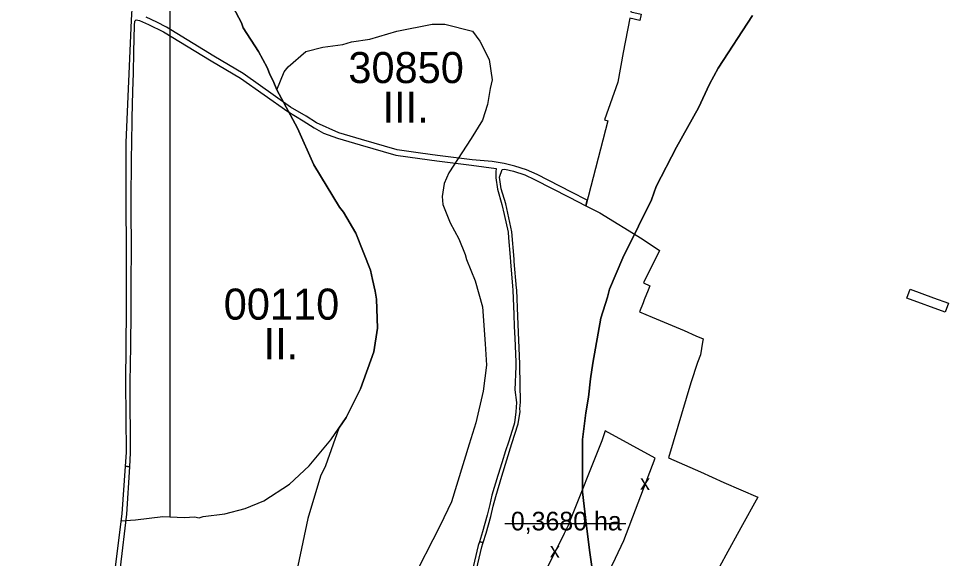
# Model space of a CAD drawing. Extents: x -555509 to -553014, y -1186753 to -1182560.
# Drawn here: x -555107 to -554508, y -1185200 to -1184853 of the extents above; entities that cross this region are included whole.
import ezdxf

# ---------------------------------------------------------------- set-up
doc = ezdxf.new("R2010")
doc.units = 0
for name, color, linetype in [('LEG_6_ZPF', 7, 'Continuous'), ('Level 29', 7, 'Continuous'), ('Level 52', 7, 'Continuous'), ('pěší_tr', 7, 'Continuous'), ('ZABOR_ke_zruseni', 7, 'Continuous')]:
    doc.layers.add(name, color=color, linetype=linetype)

msp = doc.modelspace()

# ---------------------------------------------------------------- linework, layer by layer
at = {"layer": 'LEG_6_ZPF'}
for p, q in [((-555009.53, -1184791.53), (-555009.53, -1185173.66)), ((-554656.56, -1184884.62), (-554634.5, -1184850.75)), ((-554952.5, -1184874), (-554962.25, -1184858.75)), ((-554662.06, -1184894.88), (-554656.56, -1184884.62)), ((-554669.25, -1184910.12), (-554662.06, -1184894.88)), ((-554732, -1185045.75), (-554727.75, -1185032.13)), ((-554737.12, -1185074.62), (-554732, -1185045.75))]:
    msp.add_line(p, q, dxfattribs=at)
for points in [[(-555009.53, -1184791.53), (-555000, -1184799.13), (-554997, -1184800.62), (-554988.06, -1184811.25), (-554972.38, -1184838.38), (-554963.5, -1184855.38), (-554962.25, -1184858.75), (-554952.5, -1184874), (-554946.94, -1184884.25), (-554944.88, -1184889.25), (-554943.12, -1184892.75), (-554940.62, -1184898.63)], [(-554962.25, -1184858.75), (-554963.5, -1184855.38), (-554972.38, -1184838.38), (-554988.06, -1184811.25)], [(-554634.5, -1184850.75), (-554656.56, -1184884.62), (-554662.06, -1184894.88), (-554669.25, -1184910.12), (-554683.25, -1184935.5), (-554696.38, -1184961), (-554699.38, -1184969.38), (-554707.81, -1184986.38), (-554718, -1185006.75), (-554726.5, -1185027.12), (-554727.75, -1185032.13), (-554732, -1185045.75), (-554737.12, -1185074.62), (-554738.81, -1185084.75), (-554740.06, -1185096.62), (-554741.75, -1185106.75), (-554743.88, -1185123.75), (-554743.88, -1185157.63), (-554741.31, -1185179.75), (-554739.19, -1185196.62), (-554737.12, -1185210.25)], [(-554940.62, -1184898.63), (-554935.94, -1184887.13), (-554933.38, -1184883.75), (-554921.94, -1184874), (-554910.94, -1184871.13), (-554898.19, -1184869.38), (-554892.69, -1184867.63), (-554880.81, -1184866), (-554863.44, -1184860.88), (-554840.56, -1184856.25), (-554832.5, -1184856.25), (-554814.69, -1184860.88), (-554810, -1184867.25), (-554804.06, -1184879.13), (-554801.94, -1184892.25), (-554803.25, -1184897.75), (-554804.94, -1184908), (-554808.31, -1184918.12), (-554815.5, -1184930), (-554829.94, -1184952), (-554832.94, -1184958.88), (-554834.19, -1184967.38), (-554833.75, -1184972.38), (-554829.12, -1184984.25), (-554823.56, -1184994.5), (-554819.38, -1185004.63), (-554818.5, -1185008), (-554813, -1185021.63), (-554808.31, -1185038.5), (-554806.62, -1185062.25), (-554805.75, -1185075.88), (-554807.88, -1185092.75), (-554812.56, -1185113.13), (-554816.81, -1185126.75), (-554828.25, -1185164), (-554835.44, -1185179.25), (-554854.56, -1185216.62)], [(-554940.62, -1184898.63), (-554943.12, -1184892.75), (-554944.88, -1184889.25), (-554946.94, -1184884.25), (-554952.5, -1184874)], [(-554900.75, -1185116.5), (-554896.06, -1185109.75), (-554886.75, -1185091.12), (-554878.25, -1185067.38), (-554875.75, -1185052.12), (-554876.56, -1185033.5), (-554877.44, -1185028.38), (-554879.12, -1185020.75), (-554880.38, -1185014.75), (-554889.75, -1184991), (-554897.75, -1184977.5), (-554900.31, -1184974.12), (-554916.88, -1184947), (-554927.44, -1184923.25), (-554940.62, -1184898.63)], [(-554696.38, -1184961), (-554683.25, -1184935.5), (-554669.25, -1184910.12)], [(-554707.81, -1184986.38), (-554699.38, -1184969.38), (-554696.38, -1184961)], [(-554727.75, -1185032.13), (-554726.5, -1185027.12), (-554718, -1185006.75), (-554707.81, -1184986.38)], [(-554740.06, -1185096.62), (-554738.81, -1185084.75), (-554737.12, -1185074.62)], [(-554732.88, -1185223.88), (-554737.12, -1185210.25), (-554739.19, -1185196.62), (-554741.31, -1185179.75), (-554743.88, -1185157.63), (-554743.88, -1185123.75), (-554741.75, -1185106.75), (-554740.06, -1185096.62)], [(-555009.53, -1185173.66), (-555000, -1185174), (-554993.62, -1185173.75), (-554990.62, -1185174.25), (-554988.06, -1185173.38), (-554974.12, -1185171.63), (-554960.94, -1185168.25), (-554949.06, -1185163.25), (-554932.56, -1185152.62), (-554919.81, -1185140.75), (-554905.81, -1185124.12), (-554900.75, -1185116.5)]]:
    msp.add_lwpolyline(points, dxfattribs=at)
at = {"layer": 'Level 29'}
for points in [[(-555038.12, -1184688.4), (-555038.12, -1184695.12), (-555038.56, -1184698.5), (-555036, -1184723.88), (-555031.75, -1184742.5), (-555030.06, -1184749.25), (-555026.69, -1184766.25), (-555024.12, -1184774.75), (-555015.69, -1184786.63), (-555000, -1184799.13), (-554997, -1184800.62), (-554988.06, -1184811.25), (-554972.38, -1184838.38), (-554963.5, -1184855.38), (-554962.25, -1184858.75), (-554952.5, -1184874), (-554946.94, -1184884.25), (-554944.88, -1184889.25), (-554943.12, -1184892.75), (-554940.62, -1184898.63)], [(-554634.5, -1184850.75), (-554656.56, -1184884.62), (-554662.06, -1184894.88), (-554669.25, -1184910.12), (-554683.25, -1184935.5), (-554696.38, -1184961), (-554699.38, -1184969.38), (-554707.81, -1184986.38), (-554718, -1185006.75), (-554726.5, -1185027.12), (-554727.75, -1185032.13), (-554732, -1185045.75), (-554737.12, -1185074.62), (-554738.81, -1185084.75), (-554740.06, -1185096.62), (-554741.75, -1185106.75), (-554743.88, -1185123.75), (-554743.88, -1185157.63), (-554741.31, -1185179.75), (-554739.19, -1185196.62), (-554737.12, -1185210.25)], [(-554940.62, -1184898.63), (-554935.94, -1184887.13), (-554933.38, -1184883.75), (-554921.94, -1184874), (-554910.94, -1184871.13), (-554898.19, -1184869.38), (-554892.69, -1184867.63), (-554880.81, -1184866), (-554863.44, -1184860.88), (-554840.56, -1184856.25), (-554832.5, -1184856.25), (-554814.69, -1184860.88), (-554810, -1184867.25), (-554804.06, -1184879.13), (-554801.94, -1184892.25), (-554803.25, -1184897.75), (-554804.94, -1184908), (-554808.31, -1184918.12), (-554815.5, -1184930), (-554829.94, -1184952), (-554832.94, -1184958.88), (-554834.19, -1184967.38), (-554833.75, -1184972.38), (-554829.12, -1184984.25), (-554823.56, -1184994.5), (-554819.38, -1185004.63), (-554818.5, -1185008), (-554813, -1185021.63), (-554808.31, -1185038.5), (-554806.62, -1185062.25), (-554805.75, -1185075.88), (-554807.88, -1185092.75), (-554812.56, -1185113.13), (-554816.81, -1185126.75), (-554828.25, -1185164), (-554835.44, -1185179.25), (-554854.56, -1185216.62)], [(-554940.62, -1184898.63), (-554927.44, -1184923.25), (-554916.88, -1184947), (-554900.31, -1184974.12), (-554897.75, -1184977.5), (-554889.75, -1184991), (-554880.38, -1185014.75), (-554879.12, -1185020.75), (-554877.44, -1185028.38), (-554876.56, -1185033.5), (-554875.75, -1185052.12), (-554878.25, -1185067.38), (-554886.75, -1185091.12), (-554896.06, -1185109.75), (-554900.75, -1185116.5)], [(-555040.99, -1185176.15), (-555031.75, -1185175.63), (-555014, -1185173.5), (-555000, -1185174), (-554993.62, -1185173.75), (-554990.62, -1185174.25), (-554988.06, -1185173.38), (-554974.12, -1185171.63), (-554960.94, -1185168.25), (-554949.06, -1185163.25), (-554932.56, -1185152.62), (-554919.81, -1185140.75), (-554905.81, -1185124.12), (-554900.75, -1185116.5)], [(-554900.75, -1185116.5), (-554909.25, -1185140.75), (-554912.62, -1185147.5), (-554920.69, -1185174.63), (-554930.44, -1185220.38), (-554938.06, -1185273), (-554940.62, -1185285.25)]]:
    msp.add_lwpolyline(points, dxfattribs=at)
at = {"layer": 'Level 52'}
for points in [[(-554690.37, -1184660.23), (-554694.47, -1184658.87), (-554696.6, -1184667.81), (-554697.96, -1184701.13), (-554700.16, -1184781.85), (-554712.7, -1184848.47), (-554706.04, -1184849.97), (-554706.92, -1184853.88), (-554713.44, -1184852.4), (-554717.6, -1184874.5)], [(-554717.6, -1184874.5), (-554721.19, -1184893.59), (-554729.6, -1184917.85), (-554727.63, -1184918.52), (-554741.83, -1184973.43), (-554732.66, -1184977.91)], [(-554732.66, -1184977.91), (-554705.36, -1184994.55), (-554694.27, -1185002.2), (-554704.58, -1185023.01), (-554700.42, -1185024.78), (-554701.54, -1185027.57), (-554704.08, -1185033.86), (-554704.89, -1185035.88), (-554707.18, -1185041.55), (-554699.04, -1185044.99), (-554678.5, -1185053.7), (-554670.81, -1185057.05), (-554666.18, -1185059.07), (-554666.61, -1185061.26), (-554667.89, -1185069.33), (-554669.8, -1185074.16), (-554674.12, -1185087.36), (-554688.49, -1185135.67), (-554667.86, -1185144.71), (-554652.87, -1185151.49), (-554630.97, -1185160.97)], [(-554517.89, -1185032.52), (-554508.3, -1185036.11), (-554510.48, -1185041.91), (-554535.01, -1185032.73), (-554532.83, -1185026.92), (-554517.89, -1185032.52)], [(-554630.97, -1185160.97), (-554641.88, -1185180.77), (-554651.54, -1185198.32)], [(-554651.54, -1185198.32), (-554660.04, -1185213.75), (-554661.31, -1185215.81), (-554671.87, -1185232.89), (-554682.43, -1185249.97), (-554688.42, -1185259.67), (-554691.95, -1185267.5), (-554694.99, -1185274.23)]]:
    msp.add_lwpolyline(points, dxfattribs=at)
at = {"layer": 'pěší_tr'}
for points in [[(-555043.11, -1184724.5), (-555039.16, -1184755.62), (-555035.24, -1184786.57), (-555033.83, -1184842.95), (-555034.44, -1184853.76), (-555037.85, -1184932.48), (-555037.67, -1185040.6)], [(-555011.71, -1184858.22), (-555017.83, -1184854.96), (-555024.85, -1184851.88)], [(-555035.33, -1185141.55), (-555034.78, -1185132.35), (-555035.05, -1185089.25), (-555035.03, -1185086.82), (-555034.6, -1185063.83), (-555034.36, -1185041.72), (-555034.36, -1185033.01), (-555034.36, -1185024.36), (-555034.36, -1185018.05), (-555034.31, -1185005.64), (-555034.26, -1184993.23), (-555034.35, -1184983.12), (-555034.52, -1184964.32), (-555034.3, -1184949.23), (-555034.2, -1184941.69), (-555034.09, -1184934.15), (-555033.75, -1184916.9), (-555033.34, -1184899.57), (-555033.02, -1184887.8), (-555032.65, -1184874.17), (-555032.19, -1184857.09), (-555032.12, -1184854.39), (-555031.23, -1184853.6), (-555029.16, -1184854.03), (-555023.22, -1184856.53)], [(-555023.22, -1184856.53), (-555013.54, -1184861.21)], [(-554921.84, -1184915.53), (-554931.76, -1184909.74), (-554962.24, -1184888.13), (-554981.15, -1184876.9), (-555011.71, -1184858.22)], [(-555013.54, -1184861.21), (-554982.96, -1184879.9), (-554964.15, -1184891.07), (-554933.66, -1184912.68), (-554923.6, -1184918.56)], [(-554923.6, -1184918.56), (-554916.67, -1184923.06), (-554910.54, -1184926.47), (-554901.7, -1184929.66)], [(-554900.69, -1184926.31), (-554915.02, -1184919.92), (-554921.84, -1184915.53)], [(-554901.7, -1184929.66), (-554887.09, -1184934.05), (-554864.01, -1184940.64), (-554848.56, -1184942.81), (-554837.7, -1184944.31), (-554815.34, -1184947.11)], [(-554814.9, -1184943.64), (-554837.24, -1184940.84), (-554848.08, -1184939.34), (-554863.28, -1184937.2), (-554886.1, -1184930.7), (-554900.69, -1184926.31)], [(-554815.34, -1184947.11), (-554799.47, -1184949.36)], [(-554787.34, -1184947.73), (-554794.28, -1184945.98), (-554801.99, -1184944.84), (-554814.9, -1184943.64)], [(-554750.9, -1184964.55), (-554773.15, -1184953.17), (-554779.83, -1184950.09), (-554787.34, -1184947.73)], [(-554799.47, -1184949.36), (-554799.56, -1184951.41), (-554799.72, -1184955.21), (-554798.68, -1184962.64), (-554795.8, -1184972.39), (-554794.35, -1184978.93), (-554791.8, -1184990.41), (-554791.52, -1184994.01), (-554790.54, -1185006.51), (-554790.32, -1185009.38), (-554788.92, -1185025.16), (-554788.7, -1185027.72), (-554788.07, -1185043.42), (-554787.76, -1185051.06), (-554787.46, -1185058.66), (-554786.85, -1185073.91), (-554786.74, -1185076.73), (-554787.36, -1185091.82), (-554786.33, -1185100), (-554786.54, -1185103.07), (-554786.74, -1185106), (-554787.65, -1185113.07), (-554788.12, -1185114.54), (-554791.59, -1185125.5), (-554793.37, -1185131.13), (-554795.8, -1185138.8), (-554798.2, -1185146.38), (-554798.4, -1185146.99), (-554802.15, -1185159.81), (-554803.61, -1185165.77), (-554805.28, -1185172.63), (-554808.23, -1185183.43), (-554809.52, -1185187.52), (-554810.22, -1185189.73)], [(-554807.77, -1185190.25), (-554805.84, -1185184.16), (-554802.89, -1185173.35), (-554801.29, -1185166.79), (-554799.76, -1185160.53), (-554795.9, -1185147.4), (-554789.29, -1185126.51), (-554785.26, -1185113.79), (-554784.06, -1185105.74), (-554784.14, -1185104.12), (-554783.75, -1185099.74), (-554784.25, -1185076.48), (-554784.31, -1185075.04), (-554784.92, -1185059.79), (-554785.53, -1185044.55), (-554786.21, -1185027.48), (-554786.31, -1185026.31), (-554787.83, -1185009.13), (-554787.95, -1185007.66), (-554789.31, -1184990.17), (-554793.31, -1184972.15), (-554796.19, -1184962.39), (-554797.23, -1184954.96), (-554795.5, -1184949.85)], [(-554795.5, -1184949.85), (-554793.89, -1184949.73), (-554788.39, -1184951.07)], [(-554788.39, -1184951.07), (-554781.09, -1184953.37), (-554774.68, -1184956.32), (-554752.49, -1184967.67)], [(-554740.88, -1184969.75), (-554750.9, -1184964.55)], [(-554752.49, -1184967.67), (-554741.83, -1184973.43)], [(-554741.83, -1184973.43), (-554740.88, -1184969.75)], [(-555037.67, -1185040.6), (-555038.09, -1185086.73), (-555037.6, -1185132.33), (-555038.22, -1185140.93)], [(-555038.22, -1185140.93), (-555040.43, -1185171.71), (-555049.1, -1185240.01), (-555058.64, -1185297.02), (-555070.07, -1185365.86), (-555076.4, -1185399.4), (-555083.43, -1185437.16), (-555086.38, -1185454.6), (-555089.38, -1185463.99), (-555101.61, -1185526.2), (-555105.26, -1185548.34), (-555106.28, -1185554.52), (-555106.91, -1185558.36)], [(-555054.79, -1185297.6), (-555045.36, -1185240.74), (-555037.15, -1185172.01), (-555035.33, -1185141.55)], [(-555038.22, -1185140.93), (-555035.33, -1185141.55)], [(-555035.33, -1185141.55), (-555038.22, -1185140.93)], [(-554810.22, -1185189.73), (-554810.95, -1185192.05), (-554817.98, -1185221.63)], [(-554815.55, -1185222.19), (-554808.68, -1185193.09), (-554807.98, -1185190.91), (-554807.77, -1185190.25)], [(-554810.22, -1185189.73), (-554807.77, -1185190.25)], [(-554807.77, -1185190.25), (-554810.22, -1185189.73)]]:
    msp.add_lwpolyline(points, dxfattribs=at)
at = {"layer": 'ZABOR_ke_zruseni'}
for p, q in [((-554729.32, -1185118.29), (-554731.33, -1185124.63)), ((-554697.1, -1185135.79), (-554729.32, -1185118.29)), ((-554717.35, -1185188.83), (-554697.1, -1185135.79)), ((-554722.73, -1185200.26), (-554717.35, -1185188.83)), ((-554733.33, -1185221.96), (-554722.73, -1185200.26))]:
    msp.add_line(p, q, dxfattribs=at)
for points in [[(-554731.33, -1185124.63), (-554752.6, -1185178.05), (-554753.06, -1185179.2)], [(-554793.93, -1185178.05), (-554793.93, -1185178.05), (-554715.94, -1185178.05)], [(-554753.06, -1185179.2), (-554755.68, -1185184.45), (-554769.05, -1185211.23)]]:
    msp.add_lwpolyline(points, dxfattribs=at)

# ---------------------------------------------------------------- texts
at = {"layer": 'Level 29'}
for s, p in [('30850', (-554894.61, -1184894.28)), ('III.', (-554872.58, -1184919.74)), ('00110', (-554974.85, -1185046.65)), ('II.', (-554949.18, -1185072.11))]:
    msp.add_text(s, height=20, dxfattribs=at).set_placement(p)
at = {"layer": 'ZABOR_ke_zruseni'}
for p in [(-554706.89, -1185156.22), (-554764.95, -1185199.84)]:
    msp.add_text('x', height=9.63, rotation=359.2857, dxfattribs=at).set_placement(p)
msp.add_text('0,3680 ha', height=12, dxfattribs=at).set_placement((-554790.01, -1185182.4))

doc.saveas('drawing.dxf')
